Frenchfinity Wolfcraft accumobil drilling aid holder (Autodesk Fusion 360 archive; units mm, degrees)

design "Wolfcraft accumobil drilling aid holder" references "Base"
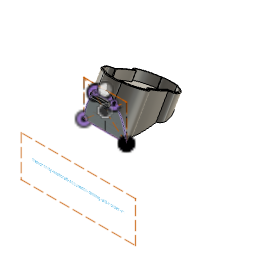
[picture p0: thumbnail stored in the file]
parameter "padding" = 1
parameter "height" = 20
parameter "wall_thickness" = 3
canvas "Canvas1"
sketch "Sketch3" plane through (0, 0, 0) normal (0, 0, 1) x axis (1, 0, 0)
  curve K1 (19.6909, 64.2538) -> (19.6909, 64.2538)
  curve K2 (20.1746, 62.3775) -> (19.2072, 66.1301)
  curve K3 (66.0714, 66.6316) -> (61.5811, 62.5665)
  curve K4 (28.4396, 56.0864) -> (6.1163, 82.4755)
  curve K5 (-11.1593, 50.1924) -> (-15.3786, 49.0863)
  curve K6 (-10.8041, 54.8711) -> (-20.2059, 42.3462)
  curve K7 (-17, 55) -> (-18.4318, 21.7574)
  curve K8 (22.5292, 74.3684) -> (-0.5292, 67.6316)
  curve K9 (-18.0319, 31.7584) -> (-8.4012, 18.4181)
  curve K10 (-2.8233, 7.0807) -> (24.0164, 1.8543)
  curve K11 (8.9827, -3.2584) -> (23.0173, 15.2584)
  curve K12 (16.7226, 8.682) -> (21.2774, 13.318)
  curve K13 (18.6253, 7.8782) -> (60.0984, 9.4682)
  curve K14 (58.8041, 13.2966) -> (65.1959, 8.7034)
  curve K15 (94.1772, 25.171) -> (97.8228, 26.829)
  curve K16 (91.7231, 24.4164) -> (102.2769, 27.5836)
  curve K17 (66.9214, -2.2354) -> (100.8763, 23.0425)
  curve K18 (97, 47.5) -> (93.7435, 51.9833)
  curve K19 (103.5, 46) -> (90.2034, 52.556)
  point P2 (19.6909, 64.2538)
  point P4 (63.8262, 64.5991)
  point P29 (17.278, 69.281)
  point P26 (-13.269, 49.6393)
  point P25 (-15.505, 48.6087)
  point P24 (-17.7159, 38.3787)
  point P28 (11, 71)
  point P22 (-13.2165, 25.0882)
  point P20 (10.5965, 4.4675)
  point P19 (16, 6)
  point P18 (19, 11)
  point P17 (39.3619, 8.6732)
  point P16 (62, 11)
  point P12 (96, 26)
  point P11 (97, 26)
  point P13 (83.8988, 10.4036)
  point P8 (95.3717, 49.7416)
  point P9 (96.8517, 49.278)
  midpoint P2 K2
  midpoint P4 K3
  midpoint P29 K4
  midpoint P26 K5
  midpoint P25 K6
  midpoint P24 K7
  midpoint P28 K8
  midpoint P22 K9
  midpoint P20 K10
  midpoint P19 K11
  midpoint P18 K12
  midpoint P17 K13
  midpoint P16 K14
  midpoint P12 K15
  midpoint P11 K16
  midpoint P13 K17
  midpoint P8 K18
  midpoint P9 K19
sketch "Sketch4" plane through (0, 0, 0) normal (0, 0, 1) x axis (1, 0, 0)
  curve K1 (19.6909, 64.2538) -> (19.6909, 64.2538)
  curve K2 (61.5285, 69.2442) -> (22.4804, 68.5691)
  curve K3 (98.8556, 52.7437) -> (61.5285, 69.2442)
  curve K4 (98.8564, 22.4395) -> (98.8556, 52.7437)
  curve K5 (59.7473, 6.933) -> (98.8564, 22.4395)
  curve K6 (21.0061, 6.4611) -> (59.7473, 6.933)
  curve K7 (-16.2736, 22.4098) -> (21.0061, 6.4611)
  curve K8 (-16.4516, 52.7918) -> (-16.2736, 22.4098)
  curve K9 (22.4804, 68.5691) -> (-16.4516, 52.7918)
  curve K10 (19.5677, 10.046) -> (61.4296, 10.1717)
  curve K11 (-14.0505, 50.4873) -> (19.5677, 10.046)
  curve K12 (20.5604, 65.0366) -> (-14.0505, 50.4873)
  curve K13 (63.2437, 65.551) -> (20.5604, 65.0366)
  curve K14 (96.2712, 50.5109) -> (63.2437, 65.551)
  curve K15 (96.6122, 24.9547) -> (96.2712, 50.5109)
  curve K16 (61.4296, 10.1717) -> (96.6122, 24.9547)
  dimension "d6" = -4 (= "( padding + wall_thickness ) * -1")
extrude "Extrude1" new body sketch "Sketch4" profile of K16 K9 along normal blind 15
extrude "Extrude2" add sketch "Sketch4" + "Sketch3" profile of S2:K1 S1:K1 S1:K16 S1:K9 blind -3 (= "wall_thickness * -1")
move "Move1"
sketch "Sketch5" plane through (0, 0, 0) normal (0, 1, 0) x axis (1, 0, 0)
  line L1 (-22.1134, 2.4046) -> (-17.3819, 5.1363)
  line L2 (16.1801, 24.5133) -> (-17.5361, 5.0473)
  line L3 (49.9967, 44.0373) -> (16.1801, 24.5133)
  line L4 (82.3229, 62.7009) -> (49.9967, 44.0373)
  line L5 (86.3819, 65.0443) -> (82.3229, 62.7009)
  line L6 (48.4541, 43.1467) -> (82.3236, 62.7013)
  line L7 (14.9032, 23.7761) -> (48.4541, 43.1467)
  line L8 (-17.3819, 5.1363) -> (14.9032, 23.7761)
  line L9 (-22.1134, 88.7751) -> (-22.1134, 2.4046)
  line L10 (-22.1134, 65.0443) -> (86.3819, 65.0443)
  point P3 (-22.1134, 2.4046)
  point P12 (-22.1134, 2.4046)
  point P8 (86.3819, 65.0443)
  point P14 (86.3819, 65.0443)
  point P15 (-22.1134, 65.0443)
  coincident P3 P12
  vertical L9
  coincident P8 P14
  coincident L9 P15
  perpendicular L9 L10
extrude "Extrude3" add of existing geometry blind 60
extrude "Extrude4" new body sketch "Sketch5" along normal blind 85 bodies "Trash (1)"
split "Split1" bodies "Trash"
work_plane "WorkPlane2" AlongDistance -63.68
split "Split2" bodies "Trash (2)"
work_plane "WorkPlane3" AlongDistance -20.744
split "Split3" bodies "Holder"
component_insert "Component Insert"
sketch "Sketch9" plane through (0, 55.6118, 0) normal (0, 1, 0) x axis (-1, 0, 0)
  line L1 (0, 52.6059) -> (-90, 52.6059)
  line L2 (0, 60) -> (0, 52.6059)
  line L3 (-90, 60) -> (0, 60)
  line L4 (-90, 52.6059) -> (-90, 60)
  line L5 (0, 60) -> (-40, 60)
extrude "Extrude5" new body of existing geometry blind 20
combine "Combine1"
move "Move2"
move "Move3"
extrude "Extrude6" add of existing geometry to an object
extrude "Extrude7" cut of existing geometry blind -41
extrude "Extrude8" add of existing geometry to an object
fillet "Fillet1" radius 1
sketch "Text" plane through (0, 55.6118, 0) normal (0, -1, 0) x axis (1, 0, 0)
  line L1 (4.622, 49.4292) -> (4.622, 47.1259)
  curve K1 (2.1659, 47.1259) -> (4.622, 49.4292)
  curve K2 (-17.3401, -2.6398) -> (2.1659, 47.1259)
  line L2 (56.822, -2.6398) -> (-17.3401, -2.6398)
  curve K3 (35.004, 49.0732) -> (56.822, -2.6398)
  line L3 (35.004, 47.1259) -> (35.004, 49.0732)
  line L4 (4.622, 47.1259) -> (35.004, 47.1259)
  line L5 (19.741, 60) -> (19.741, -2.6398)
  line L6 (-17.3401, -2.6398) -> (56.822, -2.6398)
  line L7 (-17.3401, 60) -> (-17.3401, -2.6398)
  line L8 (56.822, 60) -> (-17.3401, 60)
  line L9 (56.822, -2.6398) -> (56.822, 60)
  line L10 (-17.3401, 60) -> (56.822, -2.6398)
  line L11 (56.822, 60) -> (-17.3401, -2.6398)
  curve K4
  curve K5
  curve K6
  curve K7
  point P9 (19.741, -2.6398)
  point P15 (19.741, 28.6801)
  point P6 (56.822, -2.6398)
  point P11 (56.822, -2.6398)
  point P13 (-17.3401, 60)
  midpoint L2 P9
  perpendicular L2 L5
  horizontal L6
  perpendicular L6 L7
  parallel L6 L8
  parallel L7 L9
  coincident L10 P15
  coincident L11 P15
  coincident P6 P11
  midpoint L5 P15
  coincident P13
  dimension "d28" Text1-Height = 3
extrude "Extrude9" cut sketch "Text" against normal blind 2
sketch "Filename" plane through (0, 0, 0) normal (0, 1, 0) x axis (1, 0, 0)
  dimension "d31" = 5
named bodies: "Trash (1)", "Trash", "Trash (2)", "Holder"

design "Base"
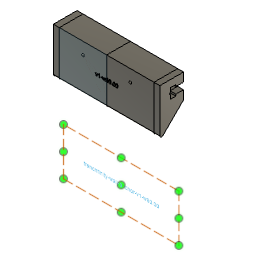
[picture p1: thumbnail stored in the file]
parameter "wall_anchor_height" = 60
parameter "wall_anchor_width" = 20
parameter "wall_anchor_angle" = 45
parameter "width_per_slot" = 40
parameter "slot_inner_width" = 8.5
parameter "slot_inner_height" = 4.5
parameter "slot_outer_width" = 5.6
parameter "slot_outer_height" = 6.5
parameter "slot_dept" = 15
parameter "print_tolerance" = 0.12
parameter "base_plate_thickness" = 16
parameter "base_plate_slot_height" = 50
parameter "wall_anchor_angle_rounded_border" = 1.5
parameter "base_plate_screw_hole_diameter" = 4
parameter "base_plate_screw_head_diameter" = 8
parameter "base_plate_screw_head_height" = 4
parameter "base_plate_screw_hole_side_distance" = 7
parameter "slot_screw_head_width" = 4.42 (= "4.3 mm + print_tolerance")
parameter "slot_screw_thread_width" = 2.12 (= "2 mm + print_tolerance")
parameter "slot_screw_head_height" = 2.12 (= "2 mm + print_tolerance")
parameter "width" = 90
parameter "filament_hole_width" = 1.7
parameter "plate_height" = 80
sketch "Side" plane through (0, 0, 0) normal (1, 0, 0) x axis (0, 1, 0)
  line L1 (39.6118, 0) -> (19.6118, 0)
  line L2 (39.6118, 60) -> (39.6118, 0)
  line L3 (19.6118, 60) -> (39.6118, 60)
  line L4 (19.6118, 0) -> (19.6118, 60)
  line L5 (39.6118, 39.6118) -> (0, 0)
  line L6 (56.0196, 0) -> (0, 0)
  point P1 (0, 0)
  point P6 (0, 0)
  point P7 (39.6118, 39.6118)
  point P2 (19.6118, 0)
  point P3 (39.6118, 0)
  point P5 (19.6118, 60)
  horizontal L1
  vertical L2
  horizontal L3
  vertical L4
  horizontal L6
  coincident P1 P6
  coincident L2 P7
  dimension "d4" distance P2 P3 = 20 (= "wall_anchor_width")
  dimension "d5" distance P2 P5 = 60 (= "wall_anchor_height")
  dimension "d6" angle L5 L6 = 45 (= "wall_anchor_angle")
extrude "Extrude1" new body sketch "Side" profile of L1 L2 L3 L4 L5 along normal blind 40 (= "width_per_slot")
sketch "Slot LeftToRight" plane through (0, 0, 0) normal (-1, 0, 0) x axis (0, -1, 0)
  line L1 (-19.6118, 60) -> (-19.6118, 19.6118)
  line L2 (-39.6118, 60) -> (-19.6118, 60)
  line L3 (-39.6118, 39.6118) -> (-39.6118, 60)
  line L4 (-19.6118, 19.6118) -> (-39.6118, 39.6118)
  line L5 (-39.6118, 52.6059) -> (-39.6118, 49.8059)
  line L6 (-39.6118, 47.0059) -> (-39.6118, 49.8059)
  line L7 (-33.1118, 52.6059) -> (-39.6118, 52.6059)
  line L8 (-28.6118, 49.8059) -> (-39.6118, 49.8059)
  line L9 (-28.6118, 54.0559) -> (-28.6118, 49.8059)
  line L10 (-33.1118, 54.0559) -> (-28.6118, 54.0559)
  line L11 (-33.1118, 52.6059) -> (-33.1118, 54.0559)
  line L12 (-28.6118, 45.5559) -> (-28.6118, 49.8059)
  line L13 (-33.1118, 45.5559) -> (-28.6118, 45.5559)
  line L14 (-33.1118, 47.0059) -> (-33.1118, 45.5559)
  line L15 (-33.1118, 47.0059) -> (-39.6118, 47.0059)
  point P6 (-39.6118, 49.8059)
  point P7 (-39.6118, 52.6059)
  point P17 (-39.6118, 47.0059)
  point P9 (-33.1118, 52.6059)
  point P16 (-33.1118, 47.0059)
  point P10 (-28.6118, 49.8059)
  point P13 (-28.6118, 49.8059)
  point P11 (-28.6118, 54.0559)
  point P14 (-28.6118, 45.5559)
  point P12 (-33.1118, 54.0559)
  point P15 (-33.1118, 45.5559)
  midpoint L3 P6
  parallel L3 L5
  parallel L3 L6
  perpendicular L3 L7
  perpendicular L6 L8
  perpendicular L8 L9
  perpendicular L9 L10
  symmetric P7 L8 P17
  symmetric P9 L8 P16
  symmetric P10 L8 P13
  symmetric L8 P11 P14
  symmetric L8 P12 P15
  dimension "d80" distance P6 P7 = 2.8 (= "slot_outer_width / 2")
  dimension "d82" distance P7 P9 = 6.5 (= "slot_outer_height")
  dimension "d84" distance P6 P10 = 11 (= "slot_outer_height + slot_inner_height")
  dimension "d85" distance P10 P11 = 4.25 (= "slot_inner_width / 2")
  dimension "d86" distance P11 P12 = 4.5 (= "slot_inner_height")
extrude "Extrude3" cut sketch "Slot LeftToRight" profile of L3 L5 L6 L7 L9 L10 L11 L12 L13 L14 L15 against normal blind 40 (magnitude of "width_per_slot * -1")
sketch "Plate" plane through (0, 39.6118, 0) normal (0, 1, 0) x axis (-1, 0, 0)
  line L1 (0, 39.6118) -> (-40, 39.6118)
  line L2 (-40, 60) -> (0, 60)
  line L3 (0, 10) -> (0, 60)
  line L4 (-40, 10) -> (-40, 60)
  line L5 (-40, 10) -> (0, 10)
  line L6 (-40, 47.0059) -> (0, 47.0059)
  line L7 (-40, 52.6059) -> (-40, 60)
  line L8 (0, 60) -> (0, 52.6059)
  line L9 (0, 52.6059) -> (-40, 52.6059)
  line L10 (-40, 60) -> (0, 60)
  line L11 (-40, 39.6118) -> (-40, 47.0059)
  line L12 (0, 47.0059) -> (0, 39.6118)
  point P2 (0, 60)
  point P3 (-40, 60)
  point P4 (0, 10)
  point P5 (-40, 10)
  perpendicular L1 L3
  perpendicular L1 L4
  dimension "d36" distance P2 P3 = 40 (= "width_per_slot")
  dimension "d37" distance P2 P4 = 50 (= "base_plate_slot_height")
  dimension "d39" distance P3 P5 = 50 (= "base_plate_slot_height")
extrude "Extrude6" new body sketch "Plate" profile of L1 L2 L3 L4 L5 L6 L7 L8 L9 L10 along normal blind 16 (= "base_plate_thickness") bodies "Base plate with slot"
sketch "Slot" plane through (0, 0, 0) normal (-1, 0, 0) x axis (0, -1, 0)
  line L1 (-19.6118, 60) -> (-19.6118, 19.6118)
  line L2 (-39.6118, 60) -> (-19.6118, 60)
  line L3 (-39.6118, 52.6059) -> (-39.6118, 60)
  line L4 (-33.1118, 52.6059) -> (-39.6118, 52.6059)
  line L5 (-33.1118, 54.0559) -> (-33.1118, 52.6059)
  line L6 (-28.6118, 54.0559) -> (-33.1118, 54.0559)
  line L7 (-28.6118, 45.5559) -> (-28.6118, 54.0559)
  line L8 (-33.1118, 45.5559) -> (-28.6118, 45.5559)
  line L9 (-33.1118, 47.0059) -> (-33.1118, 45.5559)
  line L10 (-39.6118, 47.0059) -> (-33.1118, 47.0059)
  line L11 (-39.6118, 39.6118) -> (-39.6118, 47.0059)
  line L12 (-19.6118, 19.6118) -> (-39.6118, 39.6118)
  line L13 (-33.1118, 52.6059) -> (-39.6118, 52.6059)
  line L14 (-33.1118, 54.0559) -> (-33.1118, 52.6059)
  line L15 (-28.6118, 54.0559) -> (-33.1118, 54.0559)
  line L16 (-28.6118, 45.5559) -> (-28.6118, 54.0559)
  line L17 (-33.1118, 45.5559) -> (-28.6118, 45.5559)
  line L18 (-33.1118, 47.0059) -> (-33.1118, 45.5559)
  line L19 (-39.6118, 47.0059) -> (-33.1118, 47.0059)
  line L20 (-39.6118, 10) -> (-39.6118, 60)
  line L21 (-32.9918, 52.4859) -> (-39.6118, 52.4859)
  line L22 (-32.9918, 53.9359) -> (-32.9918, 52.4859)
  line L23 (-28.7318, 53.9359) -> (-32.9918, 53.9359)
  line L24 (-28.7318, 45.6759) -> (-28.7318, 53.9359)
  line L25 (-32.9918, 45.6759) -> (-28.7318, 45.6759)
  line L26 (-32.9918, 47.1259) -> (-32.9918, 45.6759)
  line L27 (-39.6118, 47.1259) -> (-32.9918, 47.1259)
  line L28 (-33.1118, 52.6059) -> (-39.6118, 52.6059)
  line L29 (-33.1118, 52.6059) -> (-33.1118, 54.0559)
  line L30 (-28.6118, 54.0559) -> (-33.1118, 54.0559)
  line L31 (-28.6118, 45.5559) -> (-28.6118, 54.0559)
  line L32 (-33.1118, 45.5559) -> (-28.6118, 45.5559)
  line L33 (-33.1118, 47.0059) -> (-33.1118, 45.5559)
  line L34 (-39.6118, 47.0059) -> (-33.1118, 47.0059)
  line L35 (-39.6118, 47.0059) -> (-39.6118, 52.6059)
  line L36 (-49.1118, 52.6059) -> (-55.6118, 52.6059)
  line L37 (-49.1118, 52.6059) -> (-49.1118, 54.0559)
  line L38 (-44.6118, 54.0559) -> (-49.1118, 54.0559)
  line L39 (-44.6118, 45.5559) -> (-44.6118, 54.0559)
  line L40 (-49.1118, 45.5559) -> (-44.6118, 45.5559)
  line L41 (-49.1118, 47.0059) -> (-49.1118, 45.5559)
  line L42 (-55.6118, 47.0059) -> (-49.1118, 47.0059)
  line L43 (-55.6118, 47.0059) -> (-55.6118, 52.6059)
  point P15 (-39.6118, 52.6059)
  point P33 (-39.6118, 52.6059)
  point P16 (-33.1118, 52.6059)
  point P34 (-33.1118, 52.6059)
  point P17 (-33.1118, 54.0559)
  point P35 (-33.1118, 54.0559)
  point P36 (-33.1118, 52.6059)
  point P18 (-28.6118, 54.0559)
  point P37 (-28.6118, 54.0559)
  point P19 (-28.6118, 45.5559)
  point P38 (-28.6118, 45.5559)
  point P10 (-28.6118, 45.5559)
  point P39 (-28.6118, 45.5559)
  point P11 (-33.1118, 45.5559)
  point P40 (-33.1118, 45.5559)
  point P41 (-33.1118, 45.5559)
  point P12 (-33.1118, 47.0059)
  point P42 (-33.1118, 47.0059)
  point P21 (-33.1118, 47.0059)
  point P43 (-33.1118, 47.0059)
  point P22 (-39.6118, 47.0059)
  point P44 (-39.6118, 47.0059)
  point P45 (-39.6118, 52.6059)
  point P46 (-39.6118, 47.0059)
  coincident P15 P33
  coincident P16 P34
  coincident P17 P35
  coincident P16 P36
  coincident P18 P37
  coincident P19 P38
  coincident P10 P39
  coincident P11 P40
  coincident P11 P41
  coincident P12 P42
  coincident P21 P43
  coincident P22 P44
  coincident P15 P45
  coincident P22 P46
  dimension "d91" = 0.12 (= "print_tolerance")
  dimension "d96" R-Pattern1-uDistance = -16 (= "base_plate_thickness * -1")
  dimension "d97" R-Pattern1-vDistance = 0
extrude "Extrude7" add sketch "Slot" profile of L20 L24 L23 L27 L22 L25 L26 L21 against normal blind 40 (magnitude of "width_per_slot * -1")
extrude "Extrude8" cut sketch "Slot" profile of L36 L37 L38 L39 L40 L41 L42 L43 no distance stored
sketch "Sketch3" plane through (0, 0, 0) normal (-1, 0, 0) x axis (0, -1, 0)
  line L1 (-32.9918, 47.1259) -> (-39.6118, 47.1259)
  line L2 (-32.9918, 45.6759) -> (-32.9918, 47.1259)
  line L3 (-28.7318, 45.6759) -> (-32.9918, 45.6759)
  line L4 (-28.7318, 53.9359) -> (-28.7318, 45.6759)
  line L5 (-32.9918, 53.9359) -> (-28.7318, 53.9359)
  line L6 (-32.9918, 52.4859) -> (-32.9918, 53.9359)
  line L7 (-39.6118, 52.4859) -> (-32.9918, 52.4859)
  line L8 (-44.6118, 45.5559) -> (-44.6118, 54.0559)
  line L9 (-32.9918, 52.4859) -> (-39.6118, 52.4859)
  line L10 (-32.9918, 53.9359) -> (-32.9918, 52.4859)
  line L11 (-28.7318, 53.9359) -> (-32.9918, 53.9359)
  line L12 (-28.7318, 45.6759) -> (-28.7318, 53.9359)
  line L13 (-32.9918, 45.6759) -> (-28.7318, 45.6759)
  line L14 (-32.9918, 47.1259) -> (-32.9918, 45.6759)
  line L15 (-39.6118, 47.1259) -> (-32.9918, 47.1259)
  line L16 (-39.6118, 47.1259) -> (-39.6118, 52.4859)
  line L17 (-55.6118, 52.4859) -> (-48.9918, 52.4859)
  line L18 (-48.9918, 52.4859) -> (-48.9918, 53.9359)
  line L19 (-48.9918, 53.9359) -> (-44.7318, 53.9359)
  line L20 (-44.7318, 45.6759) -> (-44.7318, 53.9359)
  line L21 (-48.9918, 45.6759) -> (-44.7318, 45.6759)
  line L22 (-48.9918, 47.1259) -> (-48.9918, 45.6759)
  line L23 (-55.6118, 47.1259) -> (-48.9918, 47.1259)
  line L24 (-55.6118, 47.1259) -> (-55.6118, 52.4859)
  line L25 (-55.6118, 47.0059) -> (-49.1118, 47.0059)
  line L26 (-55.6118, 10) -> (-55.6118, 47.0059)
  line L27 (-39.6118, 10) -> (-55.6118, 10)
  line L28 (-39.6118, 47.1259) -> (-39.6118, 10)
  line L29 (-39.6118, 60) -> (-39.6118, 52.4859)
  line L30 (-55.6118, 60) -> (-39.6118, 60)
  line L31 (-55.6118, 52.6059) -> (-55.6118, 60)
  line L32 (-49.1118, 52.6059) -> (-55.6118, 52.6059)
  line L33 (-49.1118, 54.0559) -> (-49.1118, 52.6059)
  line L34 (-44.6118, 54.0559) -> (-49.1118, 54.0559)
  line L35 (-49.1118, 45.5559) -> (-44.6118, 45.5559)
  line L36 (-49.1118, 47.0059) -> (-49.1118, 45.5559)
  point P9 (-39.6118, 52.4859)
  point P20 (-39.6118, 52.4859)
  point P19 (-39.6118, 47.1259)
  point P21 (-39.6118, 47.1259)
  coincident P9 P20
  coincident P19 P21
  dimension "d105" R-Pattern1-vDistance = 0
extrude "Extrude3" new body sketch "Sketch3" profile of L17 L18 L19 L20 L21 L22 L23 L24 against normal blind 40 (magnitude of "width_per_slot * -1")
sketch "Screw hole" plane through (0, 28.6118, 0) normal (0, 1, 0) x axis (-1, 0, 0)
  line L1 (0, 54.0559) -> (0, 45.5559)
  line L2 (-40, 54.0559) -> (0, 54.0559)
  line L3 (-40, 45.5559) -> (-40, 54.0559)
  line L4 (0, 45.5559) -> (-40, 45.5559)
  line L5 (0, 45.5559) -> (-40, 54.0559)
  line L6 (-40, 45.5559) -> (0, 54.0559)
  circle C1 centre (-20, 49.8059) radius 2.21
  circle C2 centre (-20, 49.8059) radius 1.06
  point P4 (-40, 54.0559)
  point P6 (-40, 54.0559)
  point P2 (0, 45.5559)
  point P7 (0, 45.5559)
  point P3 (0, 54.0559)
  point P8 (0, 54.0559)
  point P5 (-40, 45.5559)
  point P9 (-40, 45.5559)
  point P10 (-20, 49.8059)
  coincident P4 P6
  coincident P2 P7
  coincident P3 P8
  coincident P5 P9
  midpoint L5 P10
  concentric C1 C2
  dimension "d119" diameter C1 = 4.42 (= "slot_screw_head_width")
  dimension "d120" diameter C2 = 2.12 (= "slot_screw_thread_width")
extrude "Extrude4" cut sketch "Screw hole" profile of C2 against normal blind 2000
extrude "Extrude5" cut sketch "Screw hole" profile of C1 C2 no distance stored
fillet "Fillet1" radius 1.5 (= "wall_anchor_angle_rounded_border")
work_plane "WorkPlane1" sketch "Slot LeftToRight" AlongDistance -20 (= "-width_per_slot / 2")
sketch "Screw head" plane through (20, 0, 0) normal (-1, 0, 0) x axis (0, -1, 0)
  line L1 (-28.6118, 52.0159) -> (-28.6118, 47.5959)
  line L2 (-26.4918, 52.0159) -> (-26.4918, 47.5959)
  line L3 (-26.4918, 48.7459) -> (-26.4918, 50.8659)
  line L4 (-26.4918, 50.8659) -> (-28.6118, 52.0159)
  line L5 (-26.4918, 52.0159) -> (-28.6118, 52.0159)
  point P3 (-28.6118, 52.0159)
  point P8 (-28.6118, 52.0159)
  point P6 (-26.4918, 50.8659)
  point P9 (-26.4918, 50.8659)
  point P10 (-28.6118, 52.0159)
  point P5 (-26.4918, 52.0159)
  point P11 (-26.4918, 52.0159)
  coincident P3 P8
  coincident P6 P9
  coincident P3 P10
  coincident P5 P11
revolve "Revolve1" sketch "Screw head" AlongAngle 360
sketch "Plate" plane through (0, 39.6118, 0) normal (0, 1, 0) x axis (-1, 0, 0)
  line L1 (0, 39.6118) -> (-40, 39.6118)
  line L2 (-40, 60) -> (0, 60)
  line L3 (0, 10) -> (0, 60)
  line L4 (-40, 10) -> (-40, 60)
  line L5 (-40, 10) -> (0, 10)
  line L6 (-40, 47.0059) -> (0, 47.0059)
  line L7 (-40, 39.6118) -> (-40, 47.0059)
  line L8 (0, 47.0059) -> (0, 39.6118)
  line L9 (0, 52.6059) -> (-40, 52.6059)
  line L10 (-40, 60) -> (0, 60)
  line L11 (0, 60) -> (0, 52.6059)
  line L12 (-40, 52.6059) -> (-40, 60)
  point P2 (0, 60)
  point P3 (-40, 60)
  point P4 (0, 10)
  point P5 (-40, 10)
  perpendicular L1 L3
  perpendicular L1 L4
  dimension "d36_1" distance P2 P3 = 40 (= "width_per_slot")
  dimension "d37_1" distance P2 P4 = 50 (= "base_plate_slot_height")
  dimension "d39_1" distance P3 P5 = 50 (= "base_plate_slot_height")
extrude "Extrude6" new body sketch "Plate" profile of L1 L2 L3 L4 L5 L6 L7 L8 L9 L10 along normal blind 16 (= "base_plate_thickness") named "d89_1" bodies "Base plate with slot"
sketch "Slot" plane through (0, 0, 0) normal (-1, 0, 0) x axis (0, -1, 0)
  line L1 (-19.6118, 60) -> (-19.6118, 23.2332)
  line L2 (-39.6118, 60) -> (-19.6118, 60)
  line L3 (-39.6118, 52.6059) -> (-39.6118, 60)
  line L4 (-33.1118, 52.6059) -> (-39.6118, 52.6059)
  line L5 (-33.1118, 54.0559) -> (-33.1118, 52.6059)
  line L6 (-28.6118, 54.0559) -> (-33.1118, 54.0559)
  line L7 (-28.6118, 45.5559) -> (-28.6118, 54.0559)
  line L8 (-33.1118, 45.5559) -> (-28.6118, 45.5559)
  line L9 (-33.1118, 47.0059) -> (-33.1118, 45.5559)
  line L10 (-39.6118, 47.0059) -> (-33.1118, 47.0059)
  line L11 (-39.6118, 39.6118) -> (-39.6118, 47.0059)
  line L12 (-22.1725, 22.1725) -> (-39.6118, 39.6118)
  line L13 (-33.1118, 52.6059) -> (-39.6118, 52.6059)
  line L14 (-33.1118, 54.0559) -> (-33.1118, 52.6059)
  line L15 (-28.6118, 54.0559) -> (-33.1118, 54.0559)
  line L16 (-28.6118, 45.5559) -> (-28.6118, 54.0559)
  line L17 (-33.1118, 45.5559) -> (-28.6118, 45.5559)
  line L18 (-33.1118, 47.0059) -> (-33.1118, 45.5559)
  line L19 (-39.6118, 47.0059) -> (-33.1118, 47.0059)
  line L20 (-39.6118, 10) -> (-39.6118, 60)
  line L21 (-32.9918, 52.4859) -> (-39.6118, 52.4859)
  line L22 (-32.9918, 53.9359) -> (-32.9918, 52.4859)
  line L23 (-28.7318, 53.9359) -> (-32.9918, 53.9359)
  line L24 (-28.7318, 45.6759) -> (-28.7318, 53.9359)
  line L25 (-32.9918, 45.6759) -> (-28.7318, 45.6759)
  line L26 (-32.9918, 47.1259) -> (-32.9918, 45.6759)
  line L27 (-39.6118, 47.1259) -> (-32.9918, 47.1259)
  line L28 (-33.1118, 52.6059) -> (-39.6118, 52.6059)
  line L29 (-33.1118, 52.6059) -> (-33.1118, 54.0559)
  line L30 (-28.6118, 54.0559) -> (-33.1118, 54.0559)
  line L31 (-28.6118, 45.5559) -> (-28.6118, 54.0559)
  line L32 (-33.1118, 45.5559) -> (-28.6118, 45.5559)
  line L33 (-33.1118, 47.0059) -> (-33.1118, 45.5559)
  line L34 (-39.6118, 47.0059) -> (-33.1118, 47.0059)
  line L35 (-39.6118, 47.0059) -> (-39.6118, 52.6059)
  line L36 (-49.1118, 52.6059) -> (-55.6118, 52.6059)
  line L37 (-49.1118, 52.6059) -> (-49.1118, 54.0559)
  line L38 (-44.6118, 54.0559) -> (-49.1118, 54.0559)
  line L39 (-44.6118, 45.5559) -> (-44.6118, 54.0559)
  line L40 (-49.1118, 45.5559) -> (-44.6118, 45.5559)
  line L41 (-49.1118, 47.0059) -> (-49.1118, 45.5559)
  line L42 (-55.6118, 47.0059) -> (-49.1118, 47.0059)
  line L43 (-55.6118, 47.0059) -> (-55.6118, 52.6059)
  arc A1 centre (-21.1118, 23.2332) radius 1.5 clockwise from (-19.6118, 23.2332) to (-22.1725, 22.1725)
  point P15 (-39.6118, 52.6059)
  point P33 (-39.6118, 52.6059)
  point P16 (-33.1118, 52.6059)
  point P34 (-33.1118, 52.6059)
  point P17 (-33.1118, 54.0559)
  point P35 (-33.1118, 54.0559)
  point P36 (-33.1118, 52.6059)
  point P18 (-28.6118, 54.0559)
  point P37 (-28.6118, 54.0559)
  point P19 (-28.6118, 45.5559)
  point P38 (-28.6118, 45.5559)
  point P10 (-28.6118, 45.5559)
  point P39 (-28.6118, 45.5559)
  point P11 (-33.1118, 45.5559)
  point P40 (-33.1118, 45.5559)
  point P41 (-33.1118, 45.5559)
  point P12 (-33.1118, 47.0059)
  point P42 (-33.1118, 47.0059)
  point P21 (-33.1118, 47.0059)
  point P43 (-33.1118, 47.0059)
  point P22 (-39.6118, 47.0059)
  point P44 (-39.6118, 47.0059)
  point P45 (-39.6118, 52.6059)
  point P46 (-39.6118, 47.0059)
  coincident P15 P33
  coincident P16 P34
  coincident P17 P35
  coincident P16 P36
  coincident P18 P37
  coincident P19 P38
  coincident P10 P39
  coincident P11 P40
  coincident P11 P41
  coincident P12 P42
  coincident P21 P43
  coincident P22 P44
  coincident P15 P45
  coincident P22 P46
  dimension "d91_1" = 0.12 (= "print_tolerance")
  dimension "d96_1" R-Pattern1-uDistance = -16 (= "base_plate_thickness * -1")
  dimension "d97_1" R-Pattern1-vDistance = 0
extrude "Extrude8" cut sketch "Slot" profile of L36 L37 L38 L39 L40 L41 L42 L43 no distance stored
sketch "Screw" plane through (0, 55.6118, 0) normal (0, 1, 0) x axis (-1, 0, 0)
  line L1 (-40, 47.0059) -> (0, 47.0059)
  line L2 (-40, 10) -> (-40, 47.0059)
  line L3 (0, 10) -> (-40, 10)
  line L4 (0, 47.0059) -> (0, 10)
  line L5 (-33, 17) -> (-33, 40.0059)
  line L6 (-7, 17) -> (-33, 17)
  line L7 (-7, 40.0059) -> (-7, 17)
  line L8 (-33, 40.0059) -> (-7, 40.0059)
  circle C1 centre (-33, 17) radius 4
  circle C2 centre (-33, 17) radius 2
  point P7 (-33, 17)
  point P10 (-33, 17)
  coincident P7 P10
  concentric C1 C2
  dimension "d127" = -7 (= "base_plate_screw_hole_side_distance * -1")
  dimension "d128" diameter C1 = 8
  dimension "d129" diameter C2 = 4
rectangular_pattern "R-Pattern2" countU 2 (= "floor(( width / mm ) / ( width_per_slot / cm * 10 ))") uSpaceDistance 40 (= "width_per_slot") vSpaceDistance 0 bodies "Wall anchor part (1)"
work_plane "WorkPlane2"
extrude "Extrude12" new body of existing geometry no distance stored
mirror "Mirror3" mirrorStitchTolerance 0.1
sketch "filename" plane through (0, 19.6118, 0) normal (0, -1, 0) x axis (1, 0, 0)
  dimension "d216" = 3
sketch "Text" plane through (0, 19.6118, 0) normal (0, -1, 0) x axis (1, 0, 0)
  line L1 (85, 60) -> (85, 23.2332)
  line L2 (80, 23.2332) -> (80, 60)
  line L3 (85, 23.2332) -> (80, 23.2332)
  line L4 (85, 60) -> (85, 23.2332)
  line L5 (80, 60) -> (85, 60)
  line L6 (0, 60) -> (0, 23.2332)
  line L7 (-5, 60) -> (0, 60)
  line L8 (-5, 23.2332) -> (-5, 60)
  line L9 (0, 23.2332) -> (-5, 23.2332)
  curve K1
  curve K2
  curve K3
  curve K4
  line L10 (80, 60) -> (40, 60)
  point P4 (85, 23.2332)
  point P2 (-5, 60)
  coincident P4
  coincident P2
  parallel K3 L10
  dimension "d229" Text1-Height = 3
extrude "Extrude19" cut sketch "Text" against normal blind 2
extrude "Extrude14" cut of existing geometry blind 25 (= "( width_per_slot - width ) / -2")
extrude "Extrude15" cut of existing geometry blind 25 (= "( width_per_slot - width ) / -2")
extrude "Extrude9" cut of existing geometry blind -39 (= "-width_per_slot + 1 mm")
extrude "Extrude10" add of existing geometry blind 89 (= "width - 1 mm")
extrude "Extrude13" cut of existing geometry blind -30
extrude "Extrude14" add of existing geometry blind 80 (= "plate_height")
sketch "Sketch7" plane through (0, 39.6118, 0) normal (0, -1, 0) x axis (1, 0, 0)
  dimension "d236" = 3
extrude "Extrude11" cut sketch "Sketch7" against normal blind 2
sketch "File name" plane through (0, 39.6118, 0) normal (0, -1, 0) x axis (1, 0, 0)
  line L1 (0, 47.1259) -> (90, 47.1259)
  line L2 (0, -40) -> (0, 47.1259)
  line L3 (90, 47.1259) -> (90, -40)
  curve K1
  curve K2
  curve K3
  curve K4
  line L4 (90, -40) -> (0, -40)
  curve K5 (51.4696, -0.3293) -> (52.014, -0.1533)
  curve K6 (50.7882, -0.0182) -> (51.4696, -0.3293)
  curve K7 (50.4915, 1.2014) -> (50.7882, -0.0182)
  curve K8 (53.5631, 4.3529) -> (54.1074, 4.5289)
  curve K9 (52.8817, 4.6639) -> (53.5631, 4.3529)
  curve K10 (52.5849, 5.8836) -> (52.8817, 4.6639)
  curve K11 (45.6436, -0.3293) -> (46.1879, -0.1533)
  curve K12 (44.9621, -0.0182) -> (45.6436, -0.3293)
  curve K13 (44.6654, 1.2014) -> (44.9621, -0.0182)
  curve K14 (49.1388, -0.3293) -> (49.6832, -0.1533)
  curve K15 (48.4574, -0.0182) -> (49.1388, -0.3293)
  curve K16 (48.1606, 1.2014) -> (48.4574, -0.0182)
  curve K17 (43.3189, -0.3293) -> (44.0351, -0.0673)
  curve K18 (42.6027, -0.0673) -> (43.3189, -0.3293)
  curve K19 (42.3305, 0.5896) -> (42.6027, -0.0673)
  curve K20 (42.4778, 1.0786) -> (42.3305, 0.5896)
  curve K21 (42.9014, 1.3488) -> (42.4778, 1.0786)
  curve K22 (38.1436, -0.053) -> (38.383, -0.2495)
  curve K23 (51.2323, 4.3529) -> (51.7766, 4.5289)
  curve K24 (50.5508, 4.6639) -> (51.2323, 4.3529)
  curve K25 (50.2541, 5.8836) -> (50.5508, 4.6639)
  curve K26 (52.102, 5.0302) -> (52.2104, 5.8836)
  curve K27 (51.7766, 4.5289) -> (52.102, 5.0302)
  line L5 (38.1436, -1.111) -> (38.1436, -0.053)
  line L6 (37.7752, -1.111) -> (38.1436, -1.111)
  curve K28 (38.7145, -0.3272) -> (39.1934, -0.186)
  curve K29 (38.383, -0.2495) -> (38.7145, -0.3272)
  curve K30 (50.0085, 0.3481) -> (50.117, 1.2014)
  curve K31 (49.6832, -0.1533) -> (50.0085, 0.3481)
  curve K32 (46.5133, 0.3481) -> (46.6218, 1.2014)
  curve K33 (46.1879, -0.1533) -> (46.5133, 0.3481)
  curve K34 (54.4328, 5.0302) -> (54.5413, 5.8836)
  curve K35 (54.1074, 4.5289) -> (54.4328, 5.0302)
  curve K36 (52.3394, 0.3481) -> (52.4478, 1.2014)
  curve K37 (52.014, -0.1533) -> (52.3394, 0.3481)
  curve K38 (44.7514, 4.5473) -> (45.3264, 4.3529)
  curve K39 (44.4833, 5.0978) -> (44.7514, 4.5473)
  dimension "d239" Text1-Height = 3
sketch "Sketch4" plane through (40, 0, 0) normal (1, 0, 0) x axis (0, 1, 0)
  line L1 (44.7318, 53.9359) -> (48.9918, 53.9359)
  line L2 (44.7318, 45.6759) -> (44.7318, 53.9359)
  line L3 (48.9918, 45.6759) -> (44.7318, 45.6759)
  line L4 (48.9918, 47.1259) -> (48.9918, 45.6759)
  line L5 (55.6118, 47.1259) -> (48.9918, 47.1259)
  line L6 (55.6118, 52.4859) -> (55.6118, 47.1259)
  line L7 (48.9918, 52.4859) -> (55.6118, 52.4859)
  line L8 (48.9918, 53.9359) -> (48.9918, 52.4859)
  circle C1 centre (44.7318, 49.8059) radius 0.85
  point P10 (44.7318, 49.8059)
  midpoint L2 P10
  dimension "d241" diameter C1 = 1.7 (= "filament_hole_width")
extrude "Extrude4" cut sketch "Sketch4" profile of L2 C1 no distance stored
sketch "Sketch15" plane through (-5, 0, 0) normal (-1, 0, 0) x axis (0, -1, 0)
  line L1 (-19.6118, 60) -> (-19.6118, 23.2332)
  line L2 (-39.6118, 60) -> (-19.6118, 60)
  line L3 (-39.6118, 52.6059) -> (-39.6118, 60)
  line L4 (-33.1118, 52.6059) -> (-39.6118, 52.6059)
  line L5 (-33.1118, 54.0559) -> (-33.1118, 52.6059)
  line L6 (-28.6118, 54.0559) -> (-33.1118, 54.0559)
  line L7 (-28.6118, 45.5559) -> (-28.6118, 54.0559)
  line L8 (-33.1118, 45.5559) -> (-28.6118, 45.5559)
  line L9 (-33.1118, 47.0059) -> (-33.1118, 45.5559)
  line L10 (-39.6118, 47.0059) -> (-33.1118, 47.0059)
  line L11 (-39.6118, 39.6118) -> (-39.6118, 47.0059)
  line L12 (-22.1725, 22.1725) -> (-39.6118, 39.6118)
  arc A1 centre (-21.1118, 23.2332) radius 1.5 clockwise from (-19.6118, 23.2332) to (-22.1725, 22.1725)
  circle C1 centre (-28.6118, 49.8059) radius 0.85
  point P16 (-28.6118, 49.8059)
  midpoint L7 P16
  dimension "d244" diameter C1 = 1.7 (= "filament_hole_width")
sketch "Sketch9" plane through (90, 0, 0) normal (1, 0, 0) x axis (0, 1, 0)
  line L1 (49.1118, 47.0059) -> (55.6118, 47.0059)
  line L2 (49.1118, 45.5559) -> (49.1118, 47.0059)
  line L3 (44.6118, 45.5559) -> (49.1118, 45.5559)
  line L4 (44.6118, 54.0559) -> (44.6118, 45.5559)
  line L5 (49.1118, 54.0559) -> (44.6118, 54.0559)
  line L6 (49.1118, 52.6059) -> (49.1118, 54.0559)
  line L7 (55.6118, 52.6059) -> (49.1118, 52.6059)
  line L8 (55.6118, 47.0059) -> (55.6118, -40)
  line L9 (39.6118, 60) -> (55.6118, 60)
  line L10 (39.6118, 52.4859) -> (39.6118, 60)
  line L11 (32.9918, 52.4859) -> (39.6118, 52.4859)
  line L12 (32.9918, 53.9359) -> (32.9918, 52.4859)
  line L13 (28.7318, 53.9359) -> (32.9918, 53.9359)
  line L14 (28.7318, 45.6759) -> (28.7318, 53.9359)
  line L15 (32.9918, 45.6759) -> (28.7318, 45.6759)
  line L16 (32.9918, 47.1259) -> (32.9918, 45.6759)
  line L17 (39.6118, 47.1259) -> (32.9918, 47.1259)
  line L18 (55.6118, 60) -> (55.6118, 52.6059)
  line L19 (39.6118, -40) -> (39.6118, 47.1259)
  line L20 (55.6118, -40) -> (39.6118, -40)
  circle C1 centre (28.7318, 49.8059) radius 0.85
  circle C2 centre (44.6118, 49.8059) radius 0.85
  point P20 (28.7318, 49.8059)
  point P21 (44.6118, 49.8059)
  midpoint L14 P20
  midpoint L4 P21
  dimension "d247" diameter C1 = 1.7 (= "filament_hole_width")
  dimension "d250" diameter C2 = 1.7 (= "filament_hole_width")
extrude "Extrude12" cut sketch "Sketch9" profile of L4 L14 C1 C2 no distance stored
sketch "Sketch16" plane through (0, 19.6118, 0) normal (0, -1, 0) x axis (1, 0, 0)
  dimension "d253" = 3
extrude "Extrude22" cut sketch "Sketch16" against normal blind 2
extrude "Extrude23" cut sketch "Sketch15" profile of L7 C1 against normal blind 260 and along normal blind 80
sketch "Sketch17" plane through (0, 19.6118, 0) normal (0, -1, 0) x axis (1, 0, 0)
  dimension "d258" = 3
extrude "Extrude24" cut sketch "Sketch17" against normal blind 2
extrude "Extrude26" cut sketch "Text" against normal blind 2
extrude "Extrude27" cut sketch "Text" against normal blind 2
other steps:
create_component "CreateComponent1"
create_component "CreateComponent2"
create_component "CreateComponent3"
create_component "CreateComponent4"
named bodies: "Wall anchor part", "Base plate with slot", "Wall anchor part (1)"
